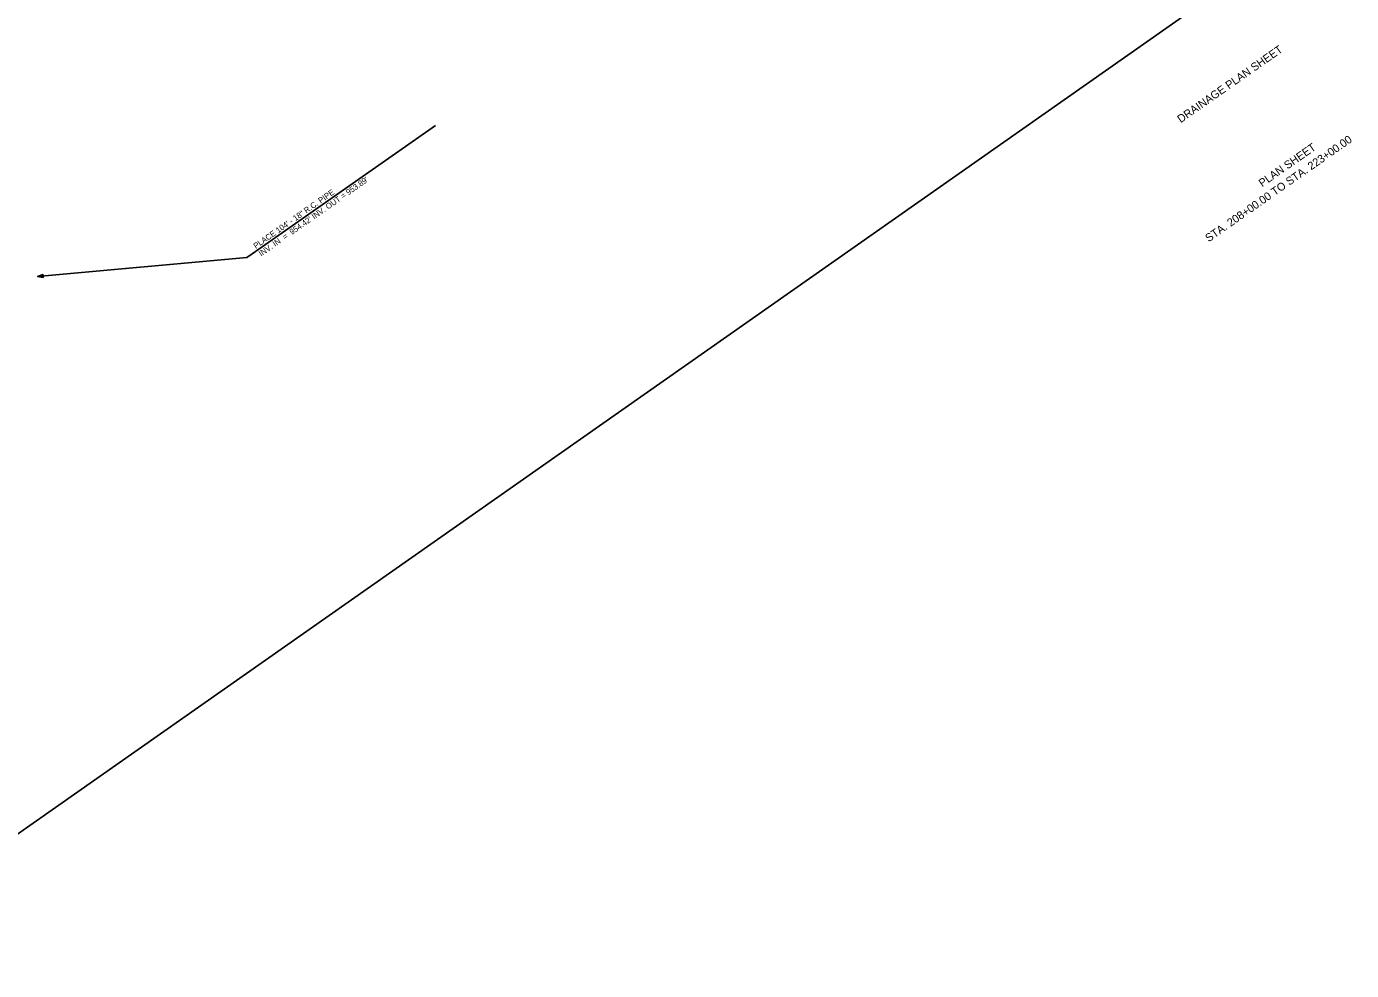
# Model space of a CAD drawing. Extents: x 1603736 to 1605697, y 1088463 to 1090389.
# Drawn here: x 1604540 to 1605697, y 1088735 to 1089559 of the extents above; entities that cross this region are included whole.
import ezdxf

# ---------------------------------------------------------------- set-up
doc = ezdxf.new("R2010")
doc.units = 0
for name, color, linetype in [('Plan_Clip', 7, 'Continuous'), ('RD_TX_Drainage', 7, 'Continuous'), ('RD_TX_RoadID', 7, 'Continuous')]:
    doc.layers.add(name, color=color, linetype=linetype)

msp = doc.modelspace()

# ---------------------------------------------------------------- linework, layer by layer
at = {"layer": 'Plan_Clip'}
msp.add_lwpolyline([(1605233.6, 1090111), (1605405.8, 1089865.4), (1605593.1, 1089598.4), (1604362.4, 1088735.2), (1604177.8, 1089004.1), (1604005.5, 1089249.7), (1603817.5, 1089517.8), (1604919, 1090290.5), (1604939.8, 1090260.9), (1605067.4, 1090350.4)], close=True, dxfattribs=at)
msp.add_lwpolyline([(1605233.6, 1090111), (1605405.8, 1089865.4), (1605593.1, 1089598.4), (1604362.4, 1088735.2), (1604177.8, 1089004.1), (1604005.5, 1089249.7), (1603817.5, 1089517.8), (1604919, 1090290.5), (1604939.8, 1090260.9), (1605067.4, 1090350.4)], close=True, dxfattribs=at)
msp.add_lwpolyline([(1605233.6, 1090111), (1605405.8, 1089865.4), (1605593.1, 1089598.4), (1604362.4, 1088735.2), (1604177.8, 1089004.1), (1604005.5, 1089249.7), (1603817.5, 1089517.8), (1604919, 1090290.5), (1604939.8, 1090260.9), (1605067.4, 1090350.4)], close=True, dxfattribs=at)
msp.add_lwpolyline([(1605233.6, 1090111), (1605405.8, 1089865.4), (1605593.1, 1089598.4), (1604362.4, 1088735.2), (1604177.8, 1089004.1), (1604005.5, 1089249.7), (1603817.5, 1089517.8), (1604919, 1090290.5), (1604939.8, 1090260.9), (1605067.4, 1090350.4)], close=True, dxfattribs=at)
msp.add_lwpolyline([(1605233.6, 1090111), (1605405.8, 1089865.4), (1605593.1, 1089598.4), (1604362.4, 1088735.2), (1604177.8, 1089004.1), (1604005.5, 1089249.7), (1603817.5, 1089517.8), (1604919, 1090290.5), (1604939.8, 1090260.9), (1605067.4, 1090350.4)], close=True, dxfattribs=at)
msp.add_lwpolyline([(1605233.6, 1090111), (1605405.8, 1089865.4), (1605593.1, 1089598.4), (1604362.4, 1088735.2), (1604177.8, 1089004.1), (1604005.5, 1089249.7), (1603817.5, 1089517.8), (1604919, 1090290.5), (1604939.8, 1090260.9), (1605067.4, 1090350.4)], close=True, dxfattribs=at)
msp.add_lwpolyline([(1605233.6, 1090111), (1605405.8, 1089865.4), (1605593.1, 1089598.4), (1604362.4, 1088735.2), (1604177.8, 1089004.1), (1604005.5, 1089249.7), (1603817.5, 1089517.8), (1604919, 1090290.5), (1604939.8, 1090260.9), (1605067.4, 1090350.4)], close=True, dxfattribs=at)
msp.add_lwpolyline([(1605233.6, 1090111), (1605405.8, 1089865.4), (1605593.1, 1089598.4), (1604362.4, 1088735.2), (1604177.8, 1089004.1), (1604005.5, 1089249.7), (1603817.5, 1089517.8), (1604919, 1090290.5), (1604939.8, 1090260.9), (1605067.4, 1090350.4)], close=True, dxfattribs=at)
at = {"layer": 'RD_TX_Drainage'}
msp.add_line((1604897, 1089472.5), (1604737.2, 1089360.5), dxfattribs=at)
msp.add_lwpolyline([(1604737.2, 1089360.5), (1604732.6, 1089357.2), (1604549.9, 1089340.8)], dxfattribs=at)
msp.add_lwpolyline([(1604554.6, 1089342.5), (1604549.9, 1089340.8), (1604554.8, 1089339.9)], close=True, dxfattribs=at)

# ---------------------------------------------------------------- texts
for s, p in [("INV. IN  =  954.42' INV. OUT = 953.89'", (1604745, 1089358)), ('PLACE 104\' - 18" R.C. PIPE', (1604740.4, 1089364.6))]:
    msp.add_text(s, height=5, rotation=35.0468, dxfattribs=at).set_placement(p)
at = {"layer": 'RD_TX_RoadID'}
for s, height, p in [('DRAINAGE PLAN SHEET', 6.983, (1605547.6, 1089474.3)), ('STA. 208+00.00 TO STA. 223+00.00', 6.983, (1605572, 1089370.4)), ('PLAN SHEET', 6.98, (1605618.7, 1089418.4))]:
    msp.add_text(s, height=height, rotation=35.0468, dxfattribs=at).set_placement(p)

doc.saveas('drawing.dxf')
